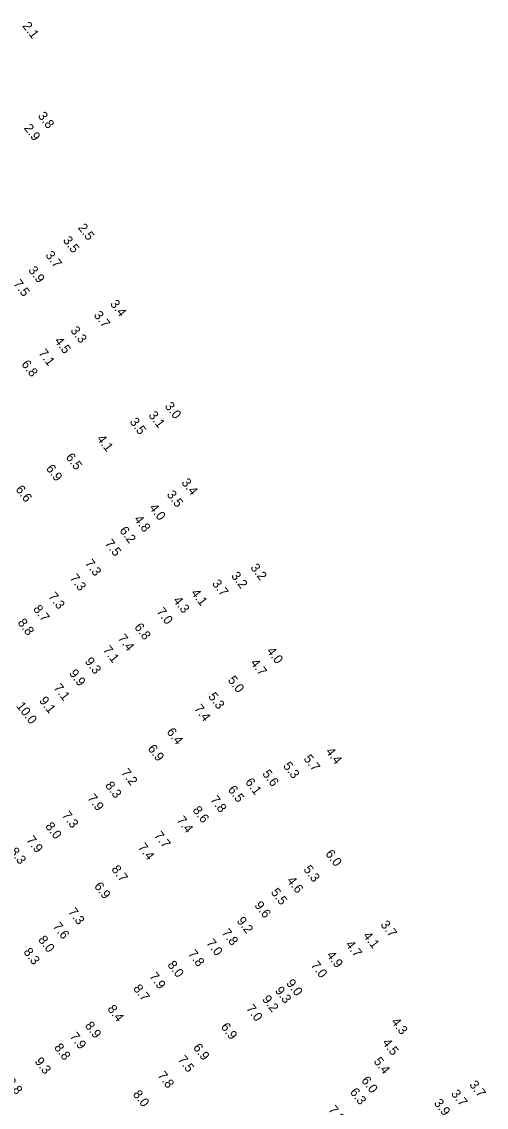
# Model space of a CAD drawing. Extents: x 815385 to 820851, y 582449 to 604245.
# Drawn here: x 819500 to 819752, y 593912 to 594501 of the extents above; entities that cross this region are included whole.
import ezdxf

# ---------------------------------------------------------------- set-up
doc = ezdxf.new("R2010")
doc.units = 0
doc.layers.add('V-TOPO-SOUN-011609', color=7, linetype='Continuous')

msp = doc.modelspace()

# ---------------------------------------------------------------- texts
at = {"layer": 'V-TOPO-SOUN-011609'}
for s, p in [('2.1', (819499.62, 594499.03)), ('3.8', (819508, 594450.17)), ('2.9', (819500.44, 594443.52)), ('2.5', (819529.73, 594389.45)), ('3.5', (819521.59, 594382.61)), ('3.7', (819512.1, 594374.52)), ('3.9', (819502.82, 594366.33)), ('7.5', (819494.69, 594358.94)), ('3.4', (819547.18, 594348.04)), ('3.7', (819538.28, 594341.92)), ('3.3', (819525.67, 594333.63)), ('4.5', (819516.97, 594327.88)), ('7.1', (819508.34, 594321.28)), ('6.8', (819499.07, 594315.3)), ('3.0', (819576.89, 594292.47)), ('3.1', (819568.03, 594287.56)), ('3.5', (819557.8, 594283.96)), ('4.1', (819539.97, 594274.73)), ('6.5', (819523.13, 594264.78)), ('6.9', (819512.4, 594258.63)), ('3.4', (819585.9, 594251.04)), ('6.6', (819495.89, 594247.27)), ('3.5', (819577.93, 594244.47)), ('4.0', (819568.41, 594237.31)), ('4.8', (819560.19, 594231.02)), ('6.2', (819552.27, 594224.9)), ('7.5', (819544.35, 594217.88)), ('7.3', (819533.54, 594207.15)), ('3.2', (819623.29, 594204.78)), ('7.3', (819525.28, 594199.08)), ('3.2', (819612.84, 594200.35)), ('3.7', (819602.49, 594196.13)), ('7.3', (819513.71, 594189.13)), ('4.3', (819581.38, 594186.95)), ('4.1', (819591.1, 594190.98)), ('8.7', (819505.43, 594182.3)), ('7.0', (819572.38, 594180.85)), ('8.8', (819497.02, 594174.89)), ('6.8', (819560.35, 594172.46)), ('7.4', (819551.38, 594166.4)), ('7.1', (819543.24, 594160.07)), ('4.0', (819632.12, 594159.43)), ('9.3', (819533.45, 594153.88)), ('4.7', (819623.34, 594153)), ('9.9', (819524.97, 594147.34)), ('5.0', (819611.02, 594143.76)), ('7.1', (819516.52, 594139.5)), ('9.1', (819508.74, 594132.54)), ('5.3', (819600.41, 594134.81)), ('10.0 ', (819496.31, 594129.64)), ('7.4', (819592.79, 594128.2)), ('6.4', (819577.87, 594115.55)), ('6.9', (819567.58, 594106.49)), ('4.4', (819664.14, 594104.92)), ('5.3', (819641.06, 594097.09)), ('5.7', (819652.18, 594101.01)), ('7.2', (819553.15, 594093.41)), ('5.6', (819629.77, 594092.81)), ('8.3', (819544.51, 594086.43)), ('6.1', (819620.49, 594088.29)), ('7.9', (819534.87, 594079.58)), ('7.8', (819601.51, 594078.7)), ('6.5', (819611.09, 594084.2)), ('7.3', (819521.11, 594070.25)), ('7.4', (819583.33, 594067.61)), ('8.6', (819591.94, 594073.04)), ('8.0', (819512.01, 594064.27)), ('7.9', (819501.79, 594056.83)), ('7.7', (819571.05, 594059.33)), ('8.3', (819492.72, 594050.59)), ('7.4', (819562.3, 594052.88)), ('6.0', (819664, 594049.37)), ('8.7', (819547.88, 594040.95)), ('5.3', (819652.1, 594040.91)), ('4.6', (819643.11, 594034.84)), ('6.9', (819538.51, 594031.74)), ('5.5', (819634.41, 594028.46)), ('9.6', (819625.49, 594021.37)), ('7.3', (819524.47, 594017.79)), ('7.6', (819516.11, 594009.94)), ('9.2', (819615.89, 594012.96)), ('3.7', (819693.89, 594010.91)), ('8.0', (819508.17, 594002.67)), ('7.8', (819607.76, 594006.5)), ('4.1', (819684.4, 594004.84)), ('7.0', (819599.35, 594000.85)), ('4.7', (819674.92, 594000.06)), ('8.3', (819500.19, 593996.04)), ('7.8', (819589.46, 593995)), ('4.9', (819664.56, 593994.33)), ('8.0', (819578.27, 593989.05)), ('7.0', (819656.06, 593988.85)), ('7.9', (819568.42, 593982.78)), ('9.0', (819642.74, 593979.03)), ('8.7', (819559.71, 593976.2)), ('9.3', (819636.61, 593975.05)), ('9.2', (819629.68, 593970.34)), ('8.4', (819545.71, 593965.09)), ('7.0', (819620.99, 593965.25)), ('8.9', (819533.5, 593956.02)), ('4.3', (819699.74, 593958.06)), ('7.9', (819525.33, 593950.16)), ('6.9', (819607.26, 593955.37)), ('8.8', (819516.82, 593944.16)), ('6.9', (819592.2, 593944.07)), ('4.5', (819694.86, 593946.77)), ('7.5', (819583.95, 593937.6)), ('9.3', (819506.26, 593936.6)), ('5.4', (819690.18, 593936.64)), ('7.8', (819572.98, 593928.96)), ('6.0', (819683.5, 593926.28)), ('9.8', (819490.79, 593925.56)), ('3.7', (819742.08, 593923.98)), ('8.0', (819559.55, 593918.79)), ('6.3', (819677.3, 593919.97)), ('3.7', (819732.16, 593919.08)), ('7.3', (819665.6, 593910.38)), ('3.9', (819722.88, 593914.01))]:
    msp.add_text(s, height=5, rotation=307.782, dxfattribs=at).set_placement(p)

doc.saveas('drawing.dxf')
